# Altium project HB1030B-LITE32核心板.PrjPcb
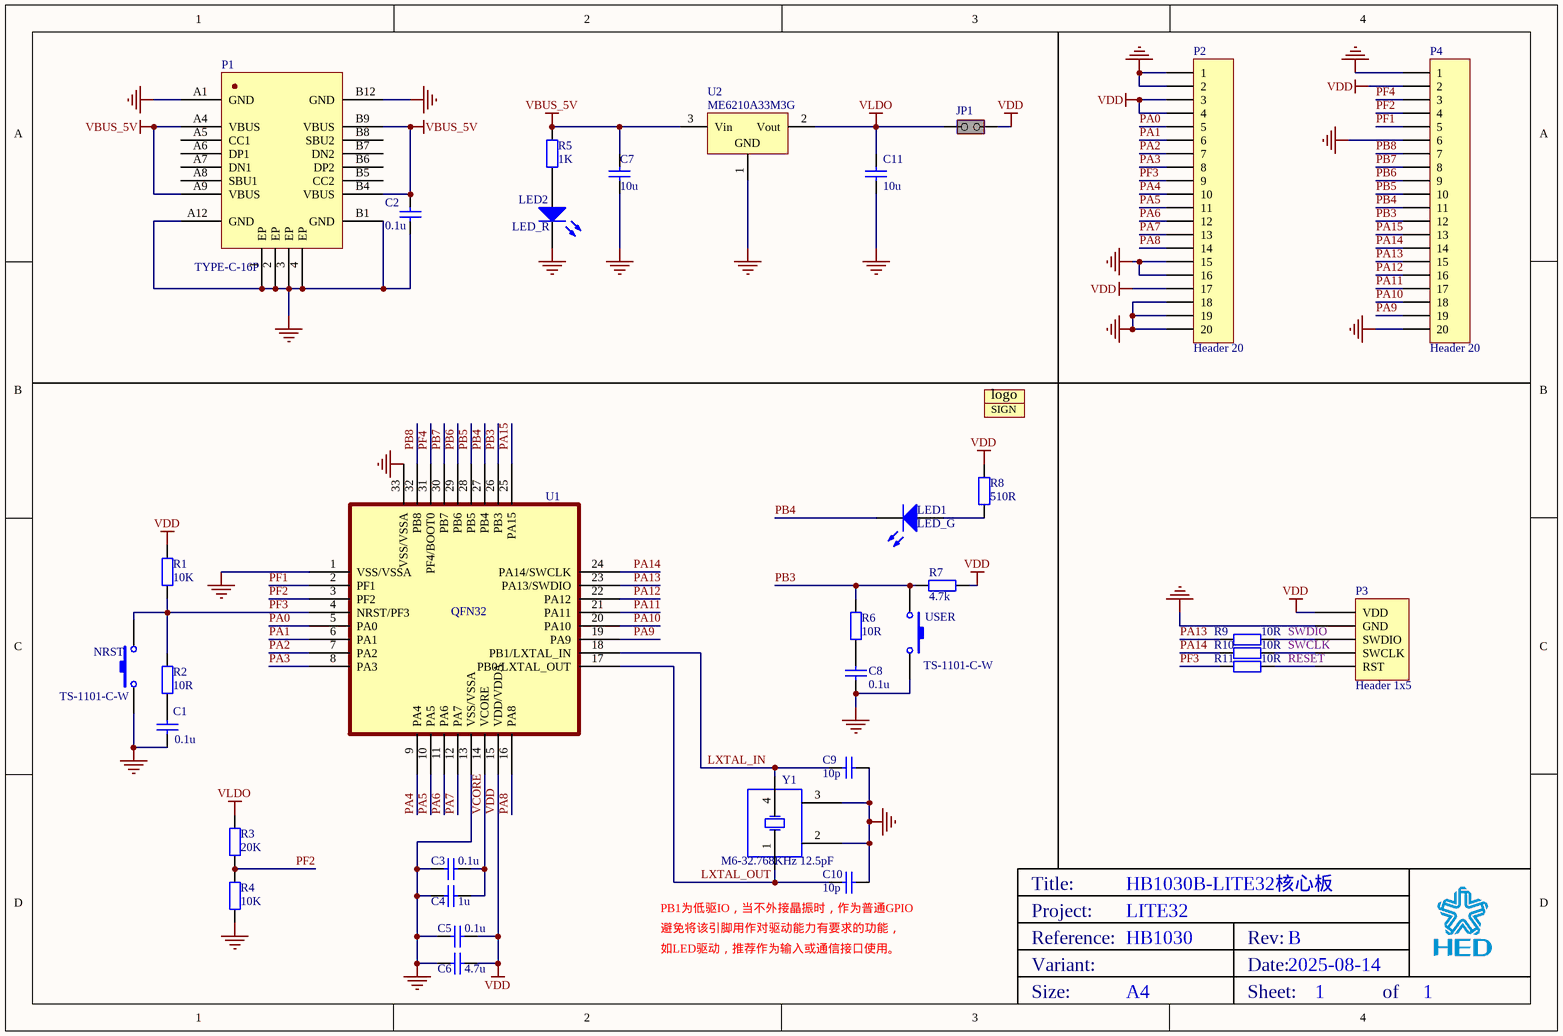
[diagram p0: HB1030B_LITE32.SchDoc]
Board_Assembly_Revision: 01; Board_Name: LITE32; Board_PCB_Revision: B; Board_Reference: HB1030
1 sheet, 36 parts. Net scope: global (net labels, ports and power ports of the same name join across sheets).
Board file: HB1030B.PcbDoc

## Sheet HB1030B_LITE32.SchDoc: HB1030B-LITE32核心板
size A4; Date: 2025-08-14; SheetNumber: 1; SheetTotal: 1

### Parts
C1  0.1u  [0402]
C2  0.1u  [0402]
C3  0.1u  [0402]
C4  1u  [0402]
C5  0.1u  [0402]
C6  4.7u  [0402]
C7  10u  [0402]
C8  0.1u  [0402]
C9  10p  [0402]
C10  10p  [0402]
C11  10u  [0402]
JP1  Header 1x2  [HEADER_1X2_2.54]  (value not drawn)
LED1  LED_G  [0603-P]
LED2  LED_R  [0603-P]
logo1  SIGN  [SIGN]  (value not drawn)
logo2  logo  [LOGO]  (value not drawn)
NRST  TS-1101-C-W  [按键_TS-1101-C-W]
P1  TYPE-C-16P  [HED-KH-TYPE-C-16P]
P2  Header 20  [HDR1X20]
P3  Header 1x5  [HDR1X5_2.54]
P4  Header 20  [HDR1X20]
R1  10K  [0402]
R2  10R  [0402]
R3  20K  [0402]
R4  10K  [0402]
R5  1K  [0402]
R6  10R  [0402]
R7  4.7k  [0402]
R8  510R  [0402]
R9  10R  [0402]
R10  10R  [0402]
R11  10R  [0402]
U1  CIU32L030K8U6  (value not drawn)
U2  ME6210A33M3G  [SOT-23-3]
USER  TS-1101-C-W  [按键_TS-1101-C-W]
Y1  M6-32.768KHz 12.5pF  [XTAL-MC146]

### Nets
GND: C1.2 C2.1 C3.2 C4.2 C5.1 C6.1 C7.1 C8.1 C9.1 C10.1 C11.1 LED2.2(K) NRST.1 P1.1(EP) P1.2(EP) P1.3(EP) P1.4(EP) P1.A1(GND) P1.A12(GND) P1.B1(GND) P1.B12(GND) P2.1 P2.2 P2.15 P2.16 P2.18 P2.19 P2.20 P3.2(GND) P4.1 P4.6 P4.20 R4.2 U1.1(VSS/VSSA) U1.13(VSS/VSSA) U1.33(VSS/VSSA) U2.1(GND) USER.1 Y1.2(OSC2) Y1.3(OSC4)
VBUS_5V: C2.2 C7.2 P1.A4(VBUS) P1.A9(VBUS) P1.B4(VBUS) P1.B9(VBUS) R5.2 U2.3(Vin)
VDD: C5.2 C6.2 JP1.1(COMMON) P2.3 P2.4 P2.17 P3.1(VDD) P4.2 R1.1 R7.2 R8.2 U1.15(VDD/VDDA)
VLDO: C11.2 JP1.2(NO) R3.2 U2.2(Vout)
LXTAL_IN: C9.2 U1.18(PB1/LXTAL_IN) Y1.4(OSC3)
LXTAL_OUT: C10.2 U1.17(PB0/LXTAL_OUT) Y1.1(OSC1)
PA0: P2.5 U1.5(PA0)
PA1: P2.6 U1.6(PA1)
PA2: P2.7 U1.7(PA2)
PA3: P2.8 U1.8(PA3)
PA4: P2.10 U1.9(PA4)
PA5: P2.11 U1.10(PA5)
PA6: P2.12 U1.11(PA6)
PA7: P2.13 U1.12(PA7)
PA8: P2.14 U1.16(PA8)
PA9: P4.19 U1.19(PA9)
PA10: P4.18 U1.20(PA10)
PA11: P4.17 U1.21(PA11)
PA12: P4.16 U1.22(PA12)
PA13: P4.15 R9.1 U1.23(PA13/SWDIO)
PA14: P4.14 R10.1 U1.24(PA14/SWCLK)
PA15: P4.13 U1.25(PA15)
PB3: P4.12 R6.2 R7.1 U1.26(PB3) USER.2
PB4: LED1.2(K) P4.11 U1.27(PB4)
PB5: P4.10 U1.28(PB5)
PB6: P4.9 U1.29(PB6)
PB7: P4.8 U1.30(PB7)
PB8: P4.7 U1.32(PB8)
PF1: P4.5 U1.2(PF1)
PF2: P4.4 R3.1 R4.1 U1.3(PF2)
PF3: NRST.2 P2.9 R1.2 R2.1 R11.1 U1.4(NRST/PF3)
PF4: P4.3 U1.31(PF4/BOOT0)
RESET: P3.5(RST) R11.2
SWCLK: P3.4(SWCLK) R10.2
SWDIO: P3.3(SWDIO) R9.2
VCORE: C3.1 C4.1 U1.14(VCORE)
NetC1_1: C1.1 R2.2
NetC8_2: C8.2 R6.1
NetLED1_1: LED1.1(A) R8.1
NetLED2_1: LED2.1(A) R5.1

Not connected (* = marked no-connect by the designer): P1 A5(CC1) A6(DP1) A7(DN1) A8(SBU1) B5(CC2) B6(DP2) B7(DN2) B8(SBU2)

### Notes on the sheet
- (near C10) PB1为低驱IO，当不外接晶振时，作为普通GPIO
- 避免将该引脚用作对驱动能力有要求的功能，
- 如LED驱动，推荐作为输入或通信接口使用。

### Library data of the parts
C1 C3-C6 C9 C10 = MCD-00211: Capacitor, MLCC, 100nF, 16V, X7R, 10%, 0603, T=0,8mm; Manufacturer_Part_Number: CC0603KRX7R7BB104; Manufacturer: YAGEO; Provided_By: Subcon; Initial_Board_Reference: mb1319
C2 = 0603 100nF 10% 50V: 贴片电容
C7 C11 = MCD-00014: Capacitor, MLCC, 10uF, 25V, X5R, 10%, 0805, T=0,85mm; Manufacturer_Part_Number: CC0805KRX5R8BB106; Manufacturer: YAGEO; Provided_By: Subcon; Initial_Board_Reference: mb1274
C8 = MCD-00211: 贴片电容; Manufacturer_Part_Number: CC0603KRX7R7BB104; Manufacturer: YAGEO; Provided_By: Subcon; Initial_Board_Reference: mb1319
JP1 = MCD-00683: Header, 2x1, 2,54mm, VR, TH, Height 5.84mm/2.54mm - Shunt Fitted by default; Part_Type: Connector; Manufacturer_Part_Number: TSW-102-07-x-S; Manufacturer: SAMTEC; Provided_By: Subcon; Initial_Board_Reference: MB1331
LED1 = LED1: 贴片LED 绿色
LED2 = LED1: 贴片LED 红色
NRST = SW-PB: Switch
P1 = KH-TYPE-C-16P: TYPE-C USB接口
P2 P4 = Header 20: Header, 20-Pin
P3 = SWD: Header, 1x5, 2,54mm, VR, TH, Height 5.84mm/2.54mm
R1 R2 R6-R11 = Res2: 贴片电阻; Value: 1K
R3 R4 = Res2: 贴片电阻; Value: 47K
R5 = Res2: 贴片电阻
U2 = ME6210: 贴片LDO3.3V; Manufacturer: 微盟电子
USER = SW-PB: 贴片按键
Y1 = MC146: 贴片晶振

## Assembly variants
None: all parts fitted
Default: all parts fitted
HB1025A_BOM: all parts fitted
